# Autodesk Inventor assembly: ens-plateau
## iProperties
Author: robert
Shininess: 41.0
Angle Display Precision: 2
Document Length Units: 11269
Document Angle Units: 11283
Document Time Units: 11279
Document Mass Units: 11290
Document Length Units Precision: 3
Document Angle Units Precision: 2
Compacted: True
PropertySet Name: _Private Model Information
Created: 2002-09
Part Number: ens-plateau
Document SubType Name: Assemblage
Designer: robert
Control State: 0
Master: False
Checked Out: False
PropertySet Name: Design Tracking Control
Density: 0.0
Volumn: 0.0
Area: 0.0
PropertySet Name: Model Information
